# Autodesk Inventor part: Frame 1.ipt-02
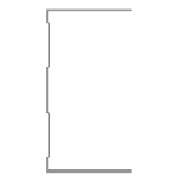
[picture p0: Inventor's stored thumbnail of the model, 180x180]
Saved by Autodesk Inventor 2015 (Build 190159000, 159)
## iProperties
IsCustomPart: 1
Created: 2015-04
Part Number: Frame 1.ipt-02
Material: Aluminum 6061
Description: Kévin Novo
Document SubType Name: Modeling
Standard: Kevin
Designer: suporte
Standards Organization: Kevin
Language: en-US
Size Designation: (Unnamed 2)
Categories: <MemberInstance><Categories><Category DisplayName="Structural Shapes" InternalName="089c4875-fa83-4c05-b084-43b9cc11f5ed" Mnemonic="GRDR"><CategoryParameter Dis
Density: 2.7 g/cm^3
Appearance: Aluminum - Flat
_CCFamilyMember: 2
_CCFamilyDisplayName: Kévin - Kévin Novo
_FrameMemberDoc: Frame Member File
_Version: 15.0.0
_GetPNFromCC: 1
G_W: 50,000 mm
G_H: 75,000 mm
G_L: 2100,000 mm
+9151D88D-7B34-404D-8A0E-9F25F6393DF7+CUTDETAIL1: Notch
Author: suporte
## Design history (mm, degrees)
node "Start Plane"
node "End Plane"
sketch "Sketch"
  geometry: L1 (24.7, 37.5)-(24.7, 36.9); L2 (24.7, 36.9)-(-24.7, 36.9); L3 (-24.7, -36.9)-(24.7, -36.9); L4 (24.7, -36.9)-(24.7, -37.5); L5 (24.7, -37.5)-(-25.3, -37.5); L6 (-25.3, 37.5)-(24.7, 37.5); L7 (-24.7, 36.9)-(-24.7, 31.9); L8 (-24.7, 31.9)-(-23.3, 30.5); L9 (-23.3, 30.5)-(-23.3, 10.934); L10 (-23.3, 10.934)-(-24.7, 9.534); L11 (-24.7, 9.534)-(-24.7, -9.534); L12 (-24.7, -9.534)-(-23.3, -10.934); L13 (-23.3, -10.934)-(-23.3, -30.5); L14 (-23.3, -30.5)-(-24.7, -31.9); L15 (-24.7, -31.9)-(-24.7, -36.9); L16 (-25.3, -37.5)-(-25.3, -31.651); L17 (-25.3, -31.651)-(-23.9, -30.251); L18 (-23.9, -30.251)-(-23.9, -11.183); L19 (-23.9, -11.183)-(-25.3, -9.783); L20 (-25.3, -9.783)-(-25.3, 9.783); L21 (-25.3, 9.783)-(-23.9, 11.183); L22 (-23.9, 11.183)-(-23.9, 30.251); L23 (-23.9, 30.251)-(-25.3, 31.651); L24 (-25.3, 31.651)-(-25.3, 37.5); L25 (-25.3, 0)-(30.37, 0); 3 further points
  constraints: 50 end point, 10 point on line, 9 parallel, 5 perpendicular, 4 equal length, 3 midpoint, 3 vertical, 2 vertical alignment, 1 collinear, 1 horizontal, 1 horizontal alignment
  dimensions: "d3" = 0.6 distance of L1.start L1.end (= d6); "d5" = 75 distance between parallel lines of L5 L6; "d6" = 0.6 distance between parallel lines of L24 L7 (= d8); "d7" = 0.6 distance between parallel lines of L8 L23 (= d8); "d8" = 0.6 distance between parallel lines of L22 L9 (= d12); "Espessura" = 0.6 distance between parallel lines of L17 L14; "d10" = 0.6 distance between parallel lines of L13 L18 (= Espessura); "d11" = 0.6 distance between parallel lines of L12 L19 (= Espessura); "d12" = 0.6 distance between parallel lines of L21 L10 (= d11); "d13" = 5 distance of L2.end L7.end; "d15" = 135 deg angle of L9 L8; "d16" = 2 distance between parallel lines of L24 L9; "d17" = 50 distance of L6.start L1.start
extrude "Body" join sketch "Sketch" stored distance "d24" = 0.13; taper "d25" = 0 deg
node "Driven Length"
  sketch "Sketch10"
    geometry: L1 (0, 0)-(10, 0) reference
    constraints: 2 end point, 1 horizontal
  workplane "Work Plane7"
  sketch "Sketch11"
    geometry: L1 (-2, 0)-(12, 0) reference; L2 (-2, 2100)-(12, 2100) reference
    dimensions: "d27" = 2100 distance between parallel lines of L1 L2 (derived)
workplane "Work Plane8"
workplane "Work Plane9"
workplane "Work Plane10"
sketch "Sketch12"
  geometry: L1 (24.7, 37.5)-(24.7, 36.9); L2 (24.7, 36.9)-(-24.7, 36.9); L3 (-24.7, 36.9)-(-24.7, 31.9); L4 (-24.7, 31.9)-(-23.3, 30.5); L5 (-23.3, 30.5)-(-23.3, 10.934); L6 (-23.3, 10.934)-(-24.7, 9.534); L7 (-24.7, 9.534)-(-24.7, -9.534); L8 (-24.7, -9.534)-(-23.3, -10.934); L9 (-23.3, -10.934)-(-23.3, -30.5); L10 (-23.3, -30.5)-(-24.7, -31.9); L11 (-24.7, -31.9)-(-24.7, -36.9); L12 (-24.7, -36.9)-(24.7, -36.9); L13 (24.7, -36.9)-(24.7, -37.5); L14 (24.7, -37.5)-(-25.3, -37.5); L15 (-25.3, -37.5)-(-25.3, -31.651); L16 (-25.3, -31.651)-(-23.9, -30.251); L17 (-23.9, -30.251)-(-23.9, -11.183); L18 (-23.9, -11.183)-(-25.3, -9.783); L19 (-25.3, -9.783)-(-25.3, 9.783); L20 (-25.3, 9.783)-(-23.9, 11.183); L21 (-23.9, 11.183)-(-23.9, 30.251); L22 (-23.9, 30.251)-(-25.3, 31.651); L23 (-25.3, 31.651)-(-25.3, 37.5); L24 (-25.3, 37.5)-(24.7, 37.5)
  constraints: 48 end point, 10 point on line
extrude "Extrusion3" cut sketch "Sketch12" stored distance "d36" = 0.13; taper "d37" = 0 deg
body "Solid1"
other parameters: "G_OFFSET_START" = 0 [user parameter; used in 1 equation term], "G_OFFSET_END" = 0 [user parameter; used in 1 equation term], "d22" = 0 (computed from G_OFFSET_START), "G_L" = 2100 (= d27) [user parameter], "d34" = 90 deg
